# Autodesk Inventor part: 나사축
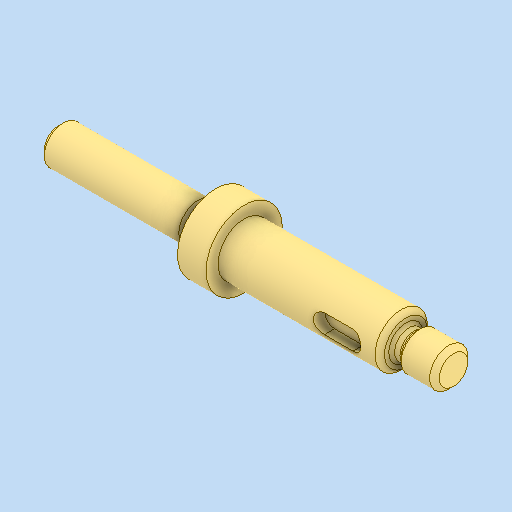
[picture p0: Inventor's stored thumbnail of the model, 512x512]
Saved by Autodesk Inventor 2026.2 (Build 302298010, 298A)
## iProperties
Created: 2026-08
Part Number: 나사축
Material: 강철, 탄소
Document SubType Name: Modeling
Designer: PC-2-06
Density: 7.85 g/cm^3
Appearance: 기본값
Author: jhkim
Sending System: Autodesk Inventor 2027
Preprocessor: ST-DEVELOPER v20.1
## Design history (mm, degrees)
feature "솔리드1"
node "솔리드2"
